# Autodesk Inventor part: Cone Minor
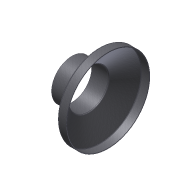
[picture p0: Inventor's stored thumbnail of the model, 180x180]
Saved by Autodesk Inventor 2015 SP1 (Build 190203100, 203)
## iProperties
Category: Mechanical Engineering Drawing and Design - CADD
Manager: Fábio Ricardo de Oliveira Souza
Company: SENAI - Serviço Nacional de Aprendizagem Industrial
Created: 2011-06
Part Number: Cone Minor
Material: Steel
Description: Stainless Steel (DIN- X6CrNiTi18-10)
Document SubType Name: Modeling
Designer: Guilherme Augusto Franco de Souza
Engineer: George Geraldo de Oliveia Silva
Authority: Fábio Ricardo de Oliveira Soza
Density: 7.85 g/cm^3
Mass: 225.023 g
Surface Area: 580.248 cm^2
Volume: 28.6654 cm^3
Appearance: Machined 02
Subject: WorldSkill 2011 - London, England
Author: Guilherme Augusto Franco de Souza
Revision Number: 00
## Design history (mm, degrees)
derived "Cone.ipt"
body "Solid2"
feature "Solid2::Cone.ipt"
tag "TaggingFeature1"
other parameters: "d8" = 1, "d9" = 1, "d10" = 2, "Diam_menor" = 72.9, "d5" = 15
